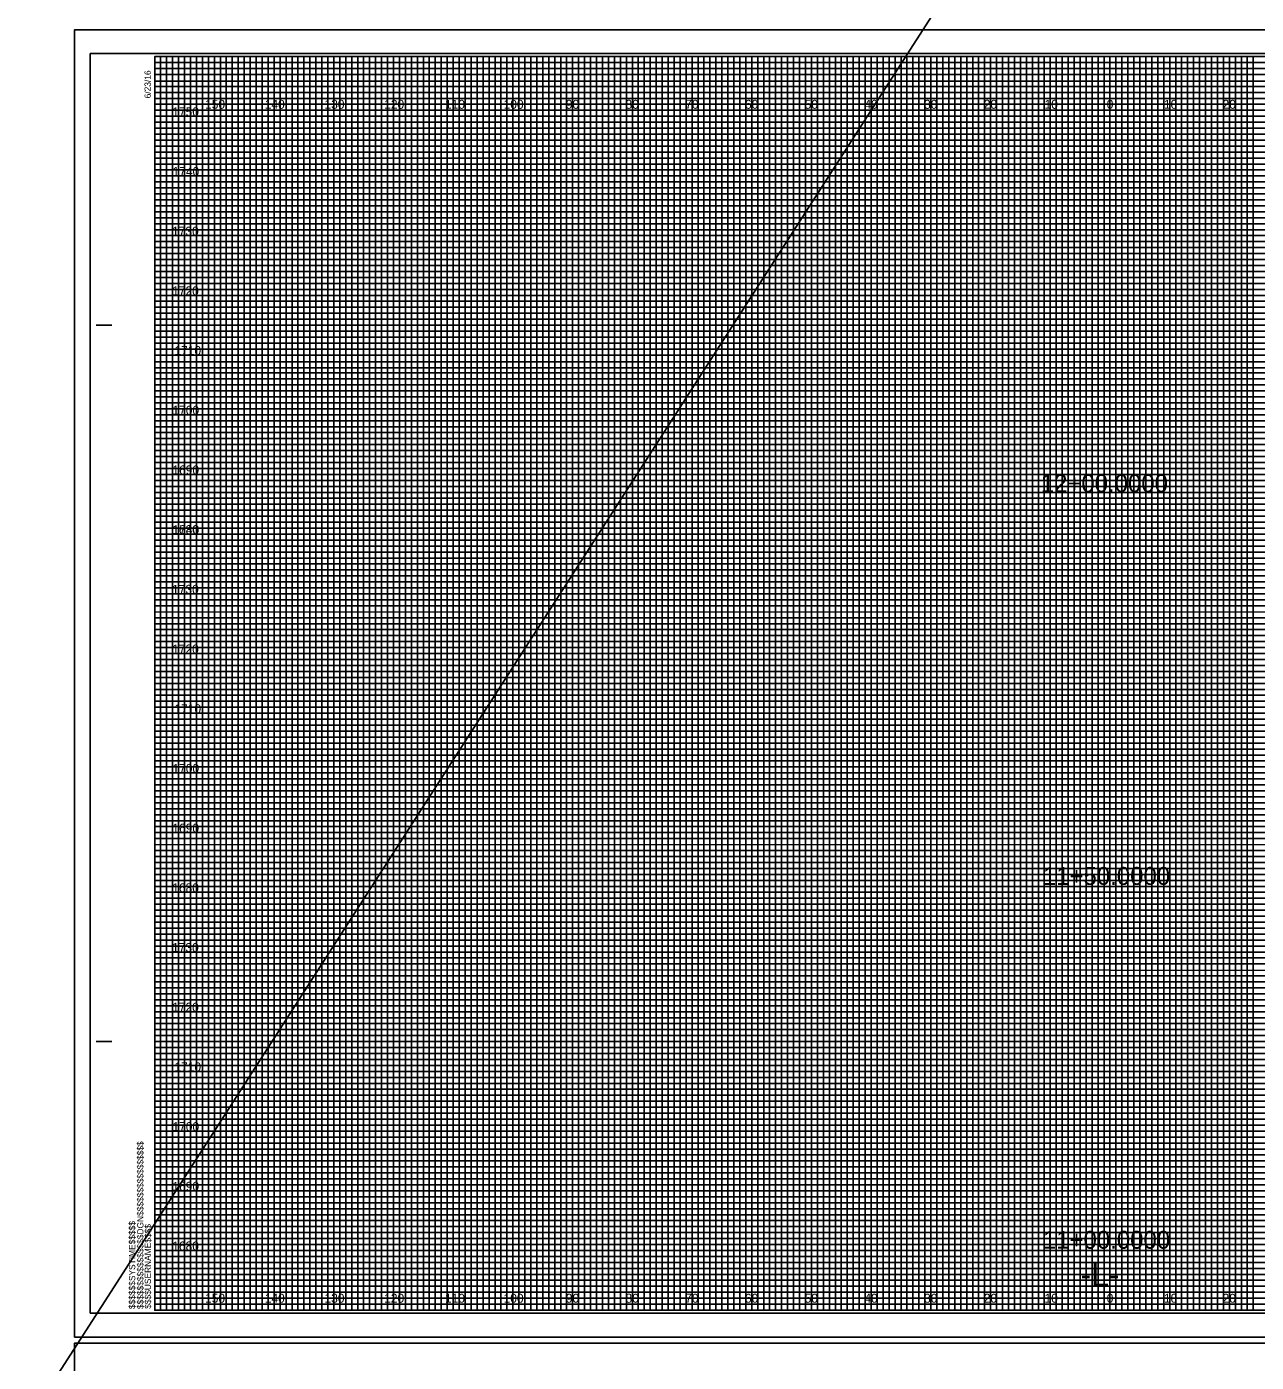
# Model space of a CAD drawing. Extents: x -419 to 4739, y -630 to 13534.
# Drawn here: x -21.4 to 184.5, y 211.3 to 435 of the extents above; entities that cross this region are included whole.
import ezdxf

# ---------------------------------------------------------------- set-up
doc = ezdxf.new("R2010")
doc.units = 0
for name, color, linetype in [('Old_Level_62', 7, 'Continuous'), ('Pattern 1', 7, 'Continuous'), ('Pattern 18', 7, 'Continuous'), ('Pattern 4', 7, 'Continuous'), ('Pattern 5', 7, 'Continuous'), ('Prop Dimension', 7, 'Continuous'), ('Prop Horizontal Alignment', 7, 'Continuous'), ('Prop PHM White Shape', 7, 'Continuous'), ('Raster_Level_0', 7, 'Continuous'), ('Scratch_Level_0', 7, 'Continuous'), ('Scratch_Level_2', 7, 'Continuous'), ('Scratch_Level_3', 7, 'Continuous'), ('Scratch_Level_5', 7, 'Continuous')]:
    doc.layers.add(name, color=color, linetype=linetype)

msp = doc.modelspace()

# ---------------------------------------------------------------- linework, layer by layer
at = {"layer": 'Old_Level_62'}
for p, q in [((-9.8, 385), (-7.3, 385)), ((-9.7, 385), (-7.2, 385)), ((-9.8, 265), (-7.3, 265)), ((-9.7, 265), (-7.2, 265)), ((0, 220), (0, 220)), ((0, 220), (0, 220)), ((0, 220), (0, 220)), ((0, 220), (0, 220)), ((0, 220), (0, 220)), ((0, 220), (0, 220)), ((0, 220), (0, 220))]:
    msp.add_line(p, q, dxfattribs=at)
msp.add_lwpolyline([(320, 430), (0, 430), (0, 220), (320, 220)], close=True, dxfattribs=at)
at = {"layer": 'Pattern 18'}
msp.add_line((-419.01, -416.83), (1573.75, 2680.65), dxfattribs=at)
for points in [[(-13.4, 215.5), (323.3, 215.5), (323.3, 434.5), (-13.4, 434.5)], [(-13.4, 434.5), (323.3, 434.5), (323.3, 215.5), (-13.4, 215.5)], [(-13.4, -4.5), (323.3, -4.5), (323.3, 214.5), (-13.4, 214.5)], [(-13.4, 214.5), (323.3, 214.5), (323.3, -4.5), (-13.4, -4.5)]]:
    msp.add_lwpolyline(points, close=True, dxfattribs=at)
at = {"layer": 'Pattern 4'}
for p, q in [((0, 429), (260, 429)), ((260, 427.98), (0, 427.98)), ((0, 427.98), (0, 427)), ((0, 427), (260, 427)), ((260, 425.89), (0, 425.89)), ((0, 425.89), (0, 424)), ((0, 424), (320, 424))]:
    msp.add_line(p, q, dxfattribs=at)
for points in [[(0, 423), (270, 423), (320, 423), (320, 422), (0, 422)], [(0, 421), (320, 421), (320, 419), (0, 419)], [(0, 418), (320, 418), (320, 417), (0, 416.98)], [(0, 416), (320, 416), (320, 414), (0, 414)], [(0, 413), (320, 413), (320, 412), (0, 412)], [(0, 411), (320, 411), (320, 409), (0, 409)], [(0, 408), (320, 408), (320, 407), (0, 407)], [(0, 406), (320, 406), (320, 404), (0, 404)], [(0, 403), (320, 403), (320, 402), (0, 402)], [(0, 401), (320, 401), (320, 399), (0, 399)], [(0, 398), (320, 398), (320, 397), (0, 397)], [(0, 396), (320, 396), (320, 393.95), (320, 393), (320, 392), (0, 392)], [(0, 394), (320, 394), (320, 393), (0, 393)], [(0, 391), (320, 391), (320, 389), (0, 389.03)], [(0, 389.03), (320, 389), (320, 388), (0, 388)], [(0, 387), (320, 387), (320, 386), (0, 386)], [(0, 384), (320, 384), (320, 383), (0, 383)], [(0, 382), (320, 382), (320, 381), (0, 381)], [(-0.07, 378.89), (320, 378.89), (320, 377.88), (-0.07, 377.88)], [(0, 377), (320, 377), (320, 376), (0, 376)], [(0, 374), (320, 374), (320, 373), (0, 373)], [(0, 372), (320, 372), (320, 371), (0, 371)], [(0, 369), (320, 369), (320, 368), (0, 368)], [(0, 367), (320, 367), (320, 366), (0, 366)], [(0, 364), (320, 364), (320, 363), (0, 363)], [(0, 362), (320, 362), (320, 361), (0, 361)], [(0, 359), (320, 359), (319.99, 357.98), (0, 358)], [(0, 357), (320, 357), (320, 356), (0, 356)], [(0, 354), (320, 354), (320, 353), (0, 353)], [(0, 352), (320, 352), (320, 351), (0, 351)], [(0, 349), (320, 349), (320, 348), (0, 348)], [(0, 347), (320, 347), (320, 346), (0, 346)], [(0, 344), (320, 344), (320, 343), (0, 343)], [(0, 342), (320, 342), (320, 341), (0, 341)], [(0, 339), (320, 339), (320, 338), (0, 338)], [(0, 336.99), (320.07, 336.91), (320, 336), (0, 336)], [(0, 334), (320, 334), (320, 333), (0, 333)], [(0, 332), (320, 332), (320, 331), (0, 331)], [(0, 329), (320, 329), (320, 328), (0, 328)], [(0, 327), (320, 327), (320, 326), (0, 326)], [(0, 324), (320, 324), (320, 323), (0, 323)], [(0, 322), (320, 322), (320, 321), (0, 321)], [(0, 319), (320, 319), (320, 318), (0, 318)], [(0, 317), (320, 317), (320, 316), (0, 316)], [(0, 314), (320, 314), (320, 313), (0, 313)], [(0, 312), (320, 312), (320, 311), (0, 311)], [(0, 309), (320, 309), (320, 308), (0, 308)], [(0, 307), (320, 307), (320, 306), (0, 306)], [(0, 304), (320, 304), (320, 303), (0, 303)], [(0, 302), (320, 302), (320, 301), (0, 301)], [(0, 299), (320, 299), (319.99, 297.98), (0, 298)], [(0, 297), (320, 297), (320, 296), (0, 296)], [(0, 294), (320, 294), (320, 293), (0, 293)], [(0, 292), (320, 292), (320, 291), (0, 291)], [(0, 289), (320, 289), (320, 288), (0, 288)], [(0, 287), (320, 287), (320, 286), (0, 286)], [(0, 284), (320, 284), (320, 283), (0, 283)], [(0, 282), (320, 282), (320, 281), (0, 281)], [(0, 279), (320, 279), (320, 278), (0, 278)], [(0, 276.99), (320.07, 276.91), (320, 276), (0, 276)], [(0, 274), (320, 274), (320, 273), (0, 273)], [(0, 272), (320, 272), (320, 271), (0, 271)], [(0, 269), (320, 269), (320, 268), (0, 268)], [(0, 267), (320, 267), (320, 266), (0, 266)], [(0, 264), (320, 264), (320, 263), (0, 263)], [(0, 262), (320, 262), (320, 261), (0, 261)], [(0, 259), (320, 259), (320, 258), (0, 258)], [(0, 257), (320, 257), (320, 256), (0, 256)], [(0, 254), (320, 254), (320, 253), (0, 253)], [(0, 252), (320, 252), (320, 251), (0, 251)], [(0, 249), (320, 249), (320, 248), (0, 248)], [(0, 247), (320, 247), (320, 246), (0, 246)], [(0, 244), (320, 244), (320, 243), (0, 243)], [(0, 242), (320, 242), (320, 241), (0, 241)], [(0, 239), (320, 239), (320, 238), (0, 238)], [(0, 237), (320, 237), (320, 236), (0, 236)], [(0, 234), (320, 234), (320, 233), (0, 233)], [(0, 232), (320, 232), (320, 231), (0, 231)], [(0, 229), (320, 229), (320, 228), (0, 228)], [(0, 227), (320, 227), (320, 226), (0, 226)], [(0, 224), (320, 224), (320, 223), (0, 223)], [(0, 222), (320, 222), (320, 221), (0, 221)]]:
    msp.add_lwpolyline(points, dxfattribs=at)
at = {"layer": 'Pattern 5'}
for p, q in [((323.3, 434.5), (-13.4, 434.5)), ((-13.4, 434.5), (-13.4, 215.5)), ((-13.4, 215.5), (323.3, 215.5)), ((323.3, 214.5), (-13.4, 214.5)), ((-13.4, 214.5), (-13.4, -4.5))]:
    msp.add_line(p, q, dxfattribs=at)
at = {"layer": 'Prop Dimension'}
for points in [[(0, 220), (1, 220), (1, 430), (2, 430), (2, 220)], [(2, 220), (3, 220), (3, 430), (4, 430), (4, 220)], [(5, 220), (6, 220), (6, 430), (7, 430), (7, 220)], [(7, 220), (8, 220), (8, 430), (9, 430), (9, 220)], [(10, 220), (11, 220), (11, 430), (12, 430), (12, 220)], [(12, 220), (13, 220), (13, 430), (14, 430), (14, 220)], [(15, 220), (16, 220), (16, 430), (17, 430), (17, 220)], [(17, 220), (18, 220), (18, 430), (19, 430), (19, 220)], [(20, 220), (21, 220), (21, 430), (22, 430), (22, 220)], [(22, 220), (23, 220), (23, 430), (24, 430), (24, 220)], [(25, 220), (26, 220), (26, 430), (27, 430), (27, 220)], [(27, 220), (28, 220), (28, 430), (29, 430), (29, 220)], [(30, 220), (31, 220), (31, 430), (32, 430), (32, 220)], [(32, 220), (33, 220), (33, 430), (34, 430), (34, 220)], [(35, 220), (36, 220), (36, 430), (37, 430), (37, 220)], [(37, 220), (38, 220), (38, 430), (39, 430), (39, 220)], [(40, 220), (41, 220), (41, 430), (42, 430), (42, 220)], [(42, 220), (43, 220), (43, 430), (44, 430), (44, 220)], [(45, 220), (46, 220), (46, 430), (47, 430), (47, 220)], [(47, 220), (48, 220), (48, 430), (49, 430), (49, 220)], [(50, 220), (51, 220), (51, 430), (52, 430), (52, 220)], [(52, 220), (53, 220), (53, 430), (54, 430), (54, 220)], [(55, 220), (56, 220), (56, 430), (57, 430), (57, 220)], [(57, 220), (58, 220), (58, 430), (59, 430), (59, 220)], [(60, 220), (61, 220), (61, 430), (62, 430), (62, 220)], [(62, 220), (63, 220), (63, 430), (64, 430), (64, 220)], [(65, 220), (66, 220), (66, 430), (67, 430), (67, 220)], [(67, 220), (68, 220), (68, 430), (69, 430), (69, 220)], [(70, 220), (71, 220), (71, 430), (72, 430), (72, 220)], [(72, 220), (73, 220), (73, 430), (74, 430), (74, 220)], [(75, 220), (76, 220), (76, 430), (77, 430), (77, 220)], [(77, 220), (78, 220), (78, 430), (79, 430), (79, 220)], [(80, 220), (81, 220), (81, 430), (82, 430), (82, 220)], [(82, 220), (83, 220), (83, 430), (84, 430), (84, 220)], [(85, 220), (86, 220), (86, 430), (87, 430), (87, 220)], [(87, 220), (88, 220), (88, 430), (89, 430), (89, 220)], [(90, 220), (91, 220), (91, 430), (92, 430), (92, 220)], [(92, 220), (93, 220), (93, 430), (94, 430), (94, 220)], [(95, 220), (96, 220), (96, 430), (97, 430), (97, 220)], [(97, 220), (98, 220), (98, 430), (99, 430), (99, 220)], [(100, 220), (101, 220), (101, 430), (102, 430), (102, 220)], [(102, 220), (103, 220), (103, 430), (104, 430), (104, 220)], [(105, 220), (106, 220), (106, 430), (107, 430), (107, 220)], [(107, 220), (108, 220), (108, 430), (109, 430), (109, 220)], [(110, 220), (111, 220), (111, 430), (112, 430), (112, 220)], [(112, 220), (113, 220), (113, 430), (114, 430), (114, 220)], [(115, 220), (116, 220), (116, 430), (117, 430), (117, 220)], [(117, 220), (118, 220), (118, 430), (119, 430), (119, 220)], [(120, 220), (121, 220), (121, 430), (122, 430), (122, 220)], [(122, 220), (123, 220), (123, 430), (124, 430), (124, 220)], [(125, 220), (126, 220), (126, 430), (127, 430), (127, 220)], [(127, 220), (128, 220), (128, 430), (129, 430), (129, 220)], [(130, 220), (131, 220), (131, 430), (132, 430), (132, 220)], [(132, 220), (133, 220), (133, 430), (134, 430), (134, 220)], [(135, 220), (136, 220), (136, 430), (137, 430), (137, 220)], [(137, 220), (138, 220), (138, 430), (139, 430), (139, 220)], [(140, 220), (141, 220), (141, 430), (142, 430), (142, 220)], [(142, 220), (143, 220), (143, 430), (144, 430), (144, 220)], [(145, 220), (146, 220), (146, 430), (147, 430), (147, 220)], [(147, 220), (148, 220), (148, 430), (149, 430), (149, 220)], [(150, 220), (151, 220), (151, 430), (152, 430), (152, 220)], [(152, 220), (153, 220), (153, 430), (154, 430), (154, 220)], [(155, 220), (156, 220), (156, 430), (157, 430), (157, 220)], [(157, 220), (158, 220), (158, 430), (159, 430), (159, 220)], [(160, 220), (161, 220), (161, 430), (162, 430), (162, 220)], [(162, 220), (163, 220), (163, 430), (164, 430), (164, 220)], [(165, 220), (166, 220), (166, 430), (167, 430), (167, 220)], [(167, 220), (168, 220), (168, 430), (169, 430), (169, 220)], [(170, 220), (171, 220), (171, 430), (172, 430), (172, 220)], [(172, 220), (173, 220), (173, 430), (174, 430), (174, 220)], [(175, 220), (176, 220), (176, 430), (177, 430), (177, 220)], [(177, 220), (178, 220), (178, 430), (179, 430), (179, 220)], [(180, 220), (181, 220), (181, 430), (182, 430), (182, 220)], [(182, 220), (183, 220), (183, 430), (184, 430), (184, 220)]]:
    msp.add_lwpolyline(points, dxfattribs=at)
at = {"layer": 'Prop Horizontal Alignment'}
for points in [[(0, 430), (5, 430), (5, 220), (15, 220), (15, 430), (25, 430), (25, 220), (35, 220), (35, 430), (45, 430), (45, 220), (55, 220), (55, 430), (65, 430), (65, 220), (75, 220), (75, 430), (85, 430), (85, 220), (95, 220), (95, 430), (105, 430), (105, 220), (115, 220), (115, 430), (125, 430), (125, 220), (135, 220), (135, 430), (145, 430), (145, 220), (155, 220), (155, 430), (165, 430), (165, 220), (175, 220), (175, 430), (185, 430)], [(0, 425), (275, 425)], [(0, 405), (320, 405), (320, 415), (0, 415)], [(0, 385), (320, 385), (320, 395), (0, 395)], [(0, 365), (320, 365), (320, 375), (0, 375)], [(0, 345), (320, 345), (320, 355), (0, 355)], [(0, 325), (320, 325), (320, 335), (0, 335)], [(0, 305), (320, 305), (320, 315), (0, 315)], [(0, 285), (320, 285), (320, 295), (0, 295)], [(0, 265), (320, 265), (320, 275), (0, 275)], [(0, 245), (320, 245), (320, 255), (0, 255)], [(0, 225), (320, 225), (320, 235), (0, 235)]]:
    msp.add_lwpolyline(points, dxfattribs=at)
at = {"layer": 'Scratch_Level_0'}
for p, q in [((10, 220), (10, 430)), ((20, 220), (20, 430)), ((30, 220), (30, 430)), ((40, 220), (40, 430)), ((50, 220), (50, 430)), ((60, 220), (60, 430)), ((70, 220), (70, 430)), ((80, 220), (80, 430)), ((90, 220), (90, 430)), ((100, 220), (100, 430)), ((110, 220), (110, 430)), ((120, 220), (120, 430)), ((130, 220), (130, 430)), ((140, 220), (140, 430)), ((150, 220), (150, 430)), ((160, 220), (160, 430)), ((170, 220), (170, 430)), ((180, 220), (180, 430)), ((0, 420), (320, 420)), ((0, 410), (320, 410)), ((0, 400), (320, 400)), ((0, 390), (320, 390)), ((0, 380), (320, 380)), ((0, 370), (320, 370)), ((0, 360), (320, 360)), ((0, 350), (320, 350)), ((0, 340), (320, 340)), ((0, 330), (320, 330)), ((0, 320), (320, 320)), ((0, 310), (320, 310)), ((0, 300), (320, 300)), ((0, 290), (320, 290)), ((0, 280), (320, 280)), ((0, 270), (320, 270)), ((0, 260), (320, 260)), ((0, 250), (320, 250)), ((0, 240), (320, 240)), ((0, 230), (320, 230))]:
    msp.add_line(p, q, dxfattribs=at)
at = {"layer": 'Scratch_Level_3'}
for p, q in [((10, 430), (0, 430)), ((10, 220), (10, 430)), ((30, 430), (20, 430)), ((20, 430), (20, 220)), ((30, 220), (30, 430)), ((50, 430), (40, 430)), ((40, 430), (40, 220)), ((50, 220), (50, 430)), ((70, 430), (60, 430)), ((60, 430), (60, 220)), ((70, 220), (70, 430)), ((90, 430), (80, 430)), ((80, 430), (80, 220)), ((90, 220), (90, 430)), ((110, 430), (100, 430)), ((100, 430), (100, 220)), ((110, 220), (110, 430)), ((130, 430), (120, 430)), ((120, 430), (120, 220)), ((130, 220), (130, 430)), ((150, 430), (140, 430)), ((140, 430), (140, 220)), ((150, 220), (150, 430)), ((170, 430), (160, 430)), ((160, 430), (160, 220)), ((170, 220), (170, 430)), ((190, 430), (180, 430)), ((180, 430), (180, 220)), ((20, 220), (10, 220)), ((40, 220), (30, 220)), ((60, 220), (50, 220)), ((80, 220), (70, 220)), ((100, 220), (90, 220)), ((120, 220), (110, 220)), ((140, 220), (130, 220)), ((160, 220), (150, 220)), ((180, 220), (170, 220))]:
    msp.add_line(p, q, dxfattribs=at)
for points in [[(0, 420), (320, 420), (320, 410), (0, 410)], [(0, 400), (320, 400), (320, 390), (0, 390)], [(0, 380), (320, 380), (320, 370), (0, 370)], [(0, 360), (320, 360), (320, 350), (0, 350)], [(0, 340), (320, 340), (320, 330), (0, 330)], [(0, 320), (320, 320), (320, 310), (0, 310)], [(0, 300), (320, 300), (320, 290), (0, 290)], [(0, 280), (320, 280), (320, 270), (0, 270)], [(0, 260), (320, 260), (320, 250), (0, 250)], [(0, 240), (320, 240), (320, 230), (0, 230)]]:
    msp.add_lwpolyline(points, dxfattribs=at)
at = {"layer": 'Scratch_Level_5'}
msp.add_lwpolyline([(-10.8, 219.5), (322.4, 219.5), (322.4, 430.5), (-10.8, 430.5)], close=True, dxfattribs=at)

# ---------------------------------------------------------------- texts
at = {"layer": 'Old_Level_62'}
for s, p in [('6/23/16', (-0.65, 423)), ('$$$$$$$$$$$$$$$$DGN$$$$$$$$$$$$$$$$', (-1.88, 220.18)), ('$$$$$$SYSTIME$$$$$', (-3.26, 220.18)), ('$$$$USERNAME$$$$', (-0.62, 220.23))]:
    msp.add_text(s, height=1.05, rotation=90, dxfattribs=at).set_placement(p)
at = {"layer": 'Pattern 1'}
for s, p in [('1750', (2.96, 420)), ('1740', (3, 410)), ('1730', (2.92, 400)), ('1720', (2.93, 390)), ('1710', (3.31, 380)), ('1700', (2.98, 370)), ('1690', (2.97, 360)), ('1680', (2.95, 350)), ('1740', (3, 350)), ('1730', (2.92, 340)), ('1720', (2.93, 330)), ('1710', (3.31, 320)), ('1700', (2.98, 310)), ('1690', (2.97, 300)), ('1680', (2.95, 290)), ('1730', (2.92, 280)), ('1720', (2.93, 270)), ('1710', (3.31, 260)), ('1700', (2.98, 250)), ('1690', (2.97, 240)), ('1680', (2.95, 230))]:
    msp.add_text(s, height=1.5, dxfattribs=at).set_placement(p)
at = {"layer": 'Prop PHM White Shape'}
msp.add_text('-L-', height=4, dxfattribs=at).set_placement((155.06, 224))
at = {"layer": 'Raster_Level_0'}
for s, p in [('150', (8.44, 421.25)), ('140', (18.44, 421.25)), ('130', (28.44, 421.25)), ('120', (38.44, 421.25)), ('110', (48.62, 421.25)), ('100', (58.44, 421.25)), ('90', (68.86, 421.25)), ('80', (78.86, 421.25)), ('70', (88.86, 421.25)), ('60', (98.86, 421.25)), ('50', (108.86, 421.25)), ('40', (118.86, 421.25)), ('30', (128.86, 421.25)), ('20', (138.86, 421.25)), ('10', (149.04, 421.25)), ('0', (159.45, 421.25)), ('0', (159.45, 421.25)), ('10', (169.04, 421.25)), ('20', (178.86, 421.25)), ('150', (8.44, 221.25)), ('140', (18.44, 221.25)), ('130', (28.44, 221.25)), ('120', (38.44, 221.25)), ('110', (48.62, 221.25)), ('100', (58.44, 221.25)), ('90', (68.86, 221.25)), ('80', (78.86, 221.25)), ('70', (88.86, 221.25)), ('60', (98.86, 221.25)), ('50', (108.86, 221.25)), ('40', (118.86, 221.25)), ('30', (128.86, 221.25)), ('20', (138.86, 221.25)), ('10', (149.04, 221.25)), ('0', (159.45, 221.25)), ('0', (159.45, 221.25)), ('10', (169.04, 221.25)), ('20', (178.86, 221.25))]:
    msp.add_text(s, height=1.5, dxfattribs=at).set_placement(p)
at = {"layer": 'Scratch_Level_2'}
for s, p in [('12+00.0000', (148.4, 357.02)), ('11+50.0000', (148.76, 291.24)), ('11+00.0000', (148.76, 230.29))]:
    msp.add_text(s, height=3, dxfattribs=at).set_placement(p)

doc.saveas('drawing.dxf')
